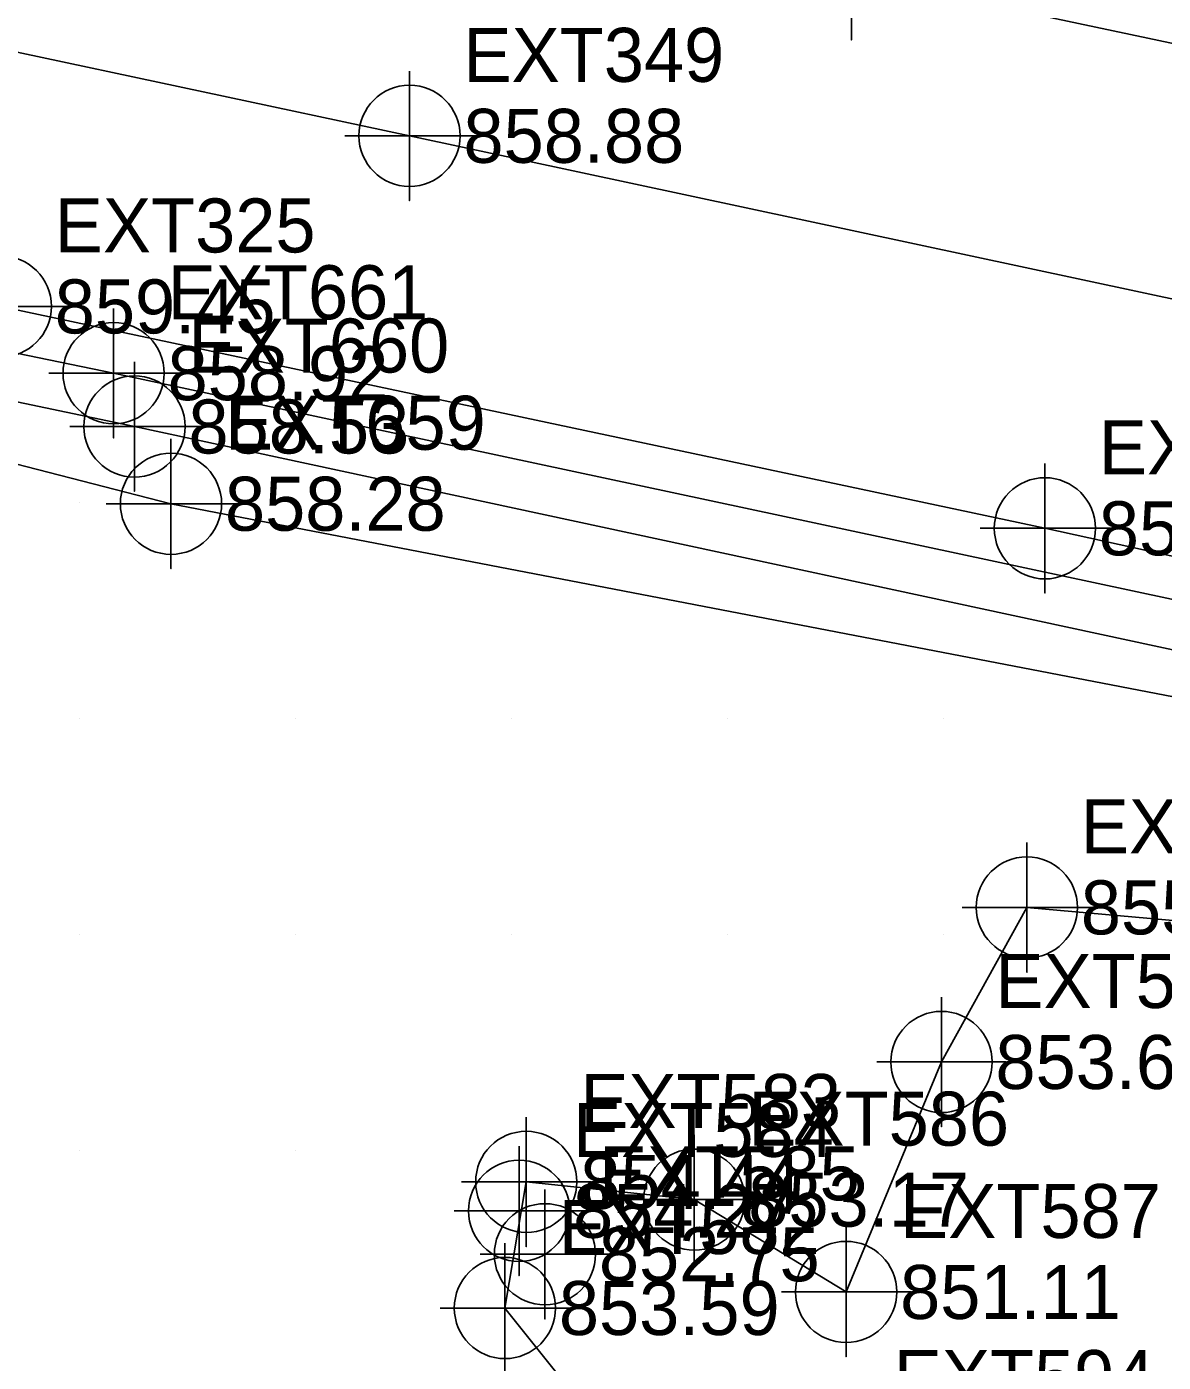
# Model space of a CAD drawing. Extents: x 1762120 to 1766775, y 709485 to 712965.
# Drawn here: x 1762697.5 to 1762750.2, y 712600.2 to 712662 of the extents above; entities that cross this region are included whole.
import ezdxf

# ---------------------------------------------------------------- set-up
doc = ezdxf.new("R2010")
doc.units = 0
for name, color, linetype in [('Exist DTM Breakline', 7, 'Continuous'), ('Exist DTM Breakline Cogo Elevation', 7, 'Continuous'), ('Exist DTM Breakline Cogo Number', 7, 'Continuous'), ('Exist DTM Breakline Cogo Point CELL', 7, 'Continuous'), ('Exist DTM Crownline', 7, 'Continuous'), ('Exist DTM Crownline Cogo Elevation', 7, 'Continuous'), ('Exist DTM Crownline Cogo Number', 7, 'Continuous'), ('Exist DTM Crownline Cogo Point CELL', 7, 'Continuous'), ('Exist DTM Drainline Cogo Elevation', 7, 'Continuous'), ('Exist DTM Drainline Cogo Number', 7, 'Continuous'), ('Exist DTM Drainline Cogo Point CELL', 7, 'Continuous'), ('Exist DTM QL2 LIDAR Elevation Point', 7, 'Continuous'), ('Exist Roads EOP', 7, 'Continuous'), ('Exist Roads EOP Cogo Elevation', 7, 'Continuous'), ('Exist Roads EOP Cogo Number', 7, 'Continuous'), ('Exist Roads EOP Cogo Point CELL', 7, 'Continuous'), ('Exist Utilities Telephone UG FO SUE LOS C', 7, 'Continuous'), ('Exist Utilities Telephone UG FO SUE LOS C Cogo Elevation', 7, 'Continuous'), ('Exist Utilities Telephone UG FO SUE LOS C Cogo Number', 7, 'Continuous'), ('Exist Utilities Telephone UG FO SUE LOS C Cogo Point CELL', 7, 'Continuous'), ('Exist Utilities Water UG Line SUE LOS C', 7, 'Continuous'), ('Exist Utilities Water UG Line SUE LOS C Cogo Elevation', 7, 'Continuous'), ('Exist Utilities Water UG Line SUE LOS C Cogo Number', 7, 'Continuous'), ('Exist Utilities Water UG Line SUE LOS C Cogo Point CELL', 7, 'Continuous')]:
    doc.layers.add(name, color=color, linetype=linetype)

msp = doc.modelspace()

# ---------------------------------------------------------------- linework, layer by layer
at = {"layer": 'Exist DTM Breakline'}
msp.add_lwpolyline([(1762719.497, 712557.512), (1762723.372, 712579.212), (1762728.166, 712592.081), (1762719.687, 712602.684), (1762720.676, 712608.523), (1762728.459, 712607.703), (1762735.491, 712603.427), (1762739.908, 712614.078), (1762743.864, 712621.238), (1762758.622, 712619.916), (1762767.954, 712615.272), (1762785.326, 712612.968), (1762818.774, 712608.043), (1762844.339, 712603.197), (1762875.474, 712595.472), (1762904.983, 712592.7), (1762941.56, 712585.948), (1762969.552, 712578.669)], dxfattribs=at)
at = {"layer": 'Exist DTM Breakline Cogo Point CELL'}
for points in [[(1762743.864, 712624.238), (1762743.864, 712618.238), (1762743.864, 712621.238), (1762746.864, 712621.238), (1762740.864, 712621.238)], [(1762739.908, 712617.078), (1762739.908, 712611.078), (1762739.908, 712614.078), (1762742.908, 712614.078), (1762736.908, 712614.078)], [(1762720.676, 712611.523), (1762720.676, 712605.523), (1762720.676, 712608.523), (1762723.676, 712608.523), (1762717.676, 712608.523)], [(1762728.459, 712610.703), (1762728.459, 712604.703), (1762728.459, 712607.703), (1762731.459, 712607.703), (1762725.459, 712607.703)], [(1762735.491, 712606.427), (1762735.491, 712600.427), (1762735.491, 712603.427), (1762738.491, 712603.427), (1762732.491, 712603.427)], [(1762719.687, 712605.684), (1762719.687, 712599.684), (1762719.687, 712602.684), (1762722.687, 712602.684), (1762716.687, 712602.684)]]:
    msp.add_lwpolyline(points, dxfattribs=at)
for centre in [(1762743.864, 712621.238), (1762739.908, 712614.078), (1762720.676, 712608.523), (1762728.459, 712607.703), (1762735.491, 712603.427), (1762719.687, 712602.684)]:
    msp.add_circle(centre, 2.344, dxfattribs=at)
at = {"layer": 'Exist DTM Crownline'}
msp.add_lwpolyline([(1762166.547, 712774.687), (1762217.293, 712763.929), (1762266.928, 712753.164), (1762315.989, 712742.645), (1762361.304, 712733.127), (1762409.518, 712722.711), (1762461.505, 712711.505), (1762512.117, 712700.307), (1762561.004, 712689.861), (1762611.478, 712678.845), (1762663.765, 712667.96), (1762715.266, 712656.972), (1762767.733, 712645.753), (1762820.16, 712634.416), (1762873.558, 712623.116), (1762907.318, 712615.867), (1762954.844, 712607.608), (1762970.656, 712604.722)], dxfattribs=at)
at = {"layer": 'Exist DTM Crownline Cogo Point CELL'}
msp.add_lwpolyline([(1762715.266, 712659.972), (1762715.266, 712653.972), (1762715.266, 712656.972), (1762718.266, 712656.972), (1762712.266, 712656.972)], dxfattribs=at)
msp.add_circle((1762715.266, 712656.972), 2.344, dxfattribs=at)
at = {"layer": 'Exist DTM Drainline Cogo Point CELL'}
for points in [[(1762720.343, 712610.184), (1762720.343, 712604.184), (1762720.343, 712607.184), (1762723.343, 712607.184), (1762717.343, 712607.184)], [(1762721.541, 712608.172), (1762721.541, 712602.172), (1762721.541, 712605.172), (1762724.541, 712605.172), (1762718.541, 712605.172)]]:
    msp.add_lwpolyline(points, dxfattribs=at)
for centre in [(1762720.343, 712607.184), (1762721.541, 712605.172)]:
    msp.add_circle(centre, 2.344, dxfattribs=at)
at = {"layer": 'Exist DTM QL2 LIDAR Elevation Point'}
for p, q in [((1762700, 712640), (1762700, 712640)), ((1762710, 712640), (1762710, 712640)), ((1762720, 712640), (1762720, 712640)), ((1762700, 712630), (1762700, 712630)), ((1762710, 712630), (1762710, 712630)), ((1762720, 712630), (1762720, 712630)), ((1762730, 712630), (1762730, 712630)), ((1762740, 712630), (1762740, 712630)), ((1762700, 712620), (1762700, 712620)), ((1762710, 712620), (1762710, 712620)), ((1762720, 712620), (1762720, 712620)), ((1762730, 712620), (1762730, 712620)), ((1762740, 712620), (1762740, 712620)), ((1762700, 712610), (1762700, 712610)), ((1762710, 712610), (1762710, 712610)), ((1762730, 712610), (1762730, 712610))]:
    msp.add_line(p, q, dxfattribs=at)
at = {"layer": 'Exist Roads EOP'}
for points in [[(1762972.643, 712616.327), (1762930.479, 712622.907), (1762881.99, 712633.196), (1762831.971, 712644.063), (1762782.816, 712654.409), (1762735.737, 712664.412), (1762686.68, 712675.525), (1762639.564, 712685.265), (1762589.399, 712696.151), (1762546.232, 712705.49), (1762496.404, 712716.081), (1762446.151, 712726.895), (1762396.234, 712737.694), (1762346.428, 712748.231), (1762295.972, 712759.182), (1762245.105, 712770.099), (1762193.683, 712780.972), (1762169.004, 712786.417)], [(1762974.578, 712585.314), (1762927.979, 712597.842), (1762890.673, 712606.296), (1762842.51, 712617.09), (1762793.23, 712628.151), (1762744.7, 712638.794), (1762696.334, 712649.071), (1762645.671, 712659.578), (1762597.313, 712669.972), (1762548.878, 712680.543), (1762499.868, 712691.039), (1762451.782, 712701.31), (1762402.083, 712712.161), (1762353.635, 712722.593), (1762304.798, 712733.112), (1762255.134, 712743.654), (1762207.339, 712753.911), (1762164.278, 712763.059), (1762150.692, 712765.782)]]:
    msp.add_lwpolyline(points, dxfattribs=at)
at = {"layer": 'Exist Roads EOP Cogo Point CELL'}
for points in [[(1762735.737, 712667.412), (1762735.737, 712661.412), (1762735.737, 712664.412), (1762738.737, 712664.412), (1762732.737, 712664.412)], [(1762696.334, 712652.071), (1762696.334, 712646.071), (1762696.334, 712649.071), (1762699.334, 712649.071), (1762693.334, 712649.071)], [(1762744.7, 712641.794), (1762744.7, 712635.794), (1762744.7, 712638.794), (1762747.7, 712638.794), (1762741.7, 712638.794)]]:
    msp.add_lwpolyline(points, dxfattribs=at)
for centre in [(1762696.334, 712649.071), (1762744.7, 712638.794)]:
    msp.add_circle(centre, 2.344, dxfattribs=at)
at = {"layer": 'Exist Utilities Telephone UG FO SUE LOS C'}
for points in [[(1762975.06, 712582.936), (1762942.128, 712590.141), (1762892.884, 712602.573), (1762845.987, 712612.29), (1762766.135, 712629.835), (1762702.526, 712643.51), (1762677.774, 712648.696)], [(1762974.378, 712580.101), (1762941.961, 712587.59), (1762882.884, 712601.621), (1762847.537, 712609.713), (1762765.896, 712628.049), (1762704.218, 712639.933), (1762682.076, 712645.625)]]:
    msp.add_lwpolyline(points, dxfattribs=at)
at = {"layer": 'Exist Utilities Telephone UG FO SUE LOS C Cogo Point CELL'}
for points in [[(1762702.526, 712646.51), (1762702.526, 712640.51), (1762702.526, 712643.51), (1762705.526, 712643.51), (1762699.526, 712643.51)], [(1762704.218, 712642.933), (1762704.218, 712636.933), (1762704.218, 712639.933), (1762707.218, 712639.933), (1762701.218, 712639.933)]]:
    msp.add_lwpolyline(points, dxfattribs=at)
for centre in [(1762702.526, 712643.51), (1762704.218, 712639.933)]:
    msp.add_circle(centre, 2.344, dxfattribs=at)
at = {"layer": 'Exist Utilities Water UG Line SUE LOS C'}
msp.add_lwpolyline([(1762975.806, 712587.967), (1762937.62, 712595.557), (1762895.763, 712604.028), (1762842.398, 712615.448), (1762766.685, 712632.078), (1762701.56, 712645.979), (1762676.599, 712651.124)], dxfattribs=at)
at = {"layer": 'Exist Utilities Water UG Line SUE LOS C Cogo Point CELL'}
msp.add_lwpolyline([(1762701.56, 712648.979), (1762701.56, 712642.979), (1762701.56, 712645.979), (1762704.56, 712645.979), (1762698.56, 712645.979)], dxfattribs=at)
msp.add_circle((1762701.56, 712645.979), 2.344, dxfattribs=at)

# ---------------------------------------------------------------- texts
at = {"layer": 'Exist DTM Breakline Cogo Elevation'}
for s, p in [('855.14', (1762746.364, 712619.988)), ('853.67', (1762742.408, 712612.828)), ('854.44', (1762723.176, 712607.273)), ('853.17', (1762730.959, 712606.453)), ('851.11', (1762737.991, 712602.177)), ('853.59', (1762722.187, 712601.434))]:
    msp.add_text(s, height=2.5, dxfattribs=at).set_placement(p)
at = {"layer": 'Exist DTM Breakline Cogo Number'}
for s, p in [('EXT589', (1762746.364, 712623.738)), ('EXT588', (1762742.408, 712616.578)), ('EXT583', (1762723.176, 712611.023)), ('EXT586', (1762730.959, 712610.203)), ('EXT587', (1762737.991, 712605.927)), ('EXT582', (1762722.187, 712605.184))]:
    msp.add_text(s, height=2.5, dxfattribs=at).set_placement(p)
at = {"layer": 'Exist DTM Crownline Cogo Elevation'}
msp.add_text('858.88', height=2.5, dxfattribs=at).set_placement((1762717.766, 712655.722))
at = {"layer": 'Exist DTM Crownline Cogo Number'}
msp.add_text('EXT349', height=2.5, dxfattribs=at).set_placement((1762717.766, 712659.472))
at = {"layer": 'Exist DTM Drainline Cogo Elevation'}
for s, p in [('854.27', (1762722.843, 712605.934)), ('852.75', (1762724.041, 712603.922))]:
    msp.add_text(s, height=2.5, dxfattribs=at).set_placement(p)
at = {"layer": 'Exist DTM Drainline Cogo Number'}
for s, p in [('EXT584', (1762722.843, 712609.684)), ('EXT585', (1762724.041, 712607.672)), ('EXT594', (1762737.699, 712598.236))]:
    msp.add_text(s, height=2.5, dxfattribs=at).set_placement(p)
at = {"layer": 'Exist Roads EOP Cogo Elevation'}
for s, p in [('859.45', (1762698.834, 712647.821)), ('857.21', (1762747.2, 712637.544))]:
    msp.add_text(s, height=2.5, dxfattribs=at).set_placement(p)
at = {"layer": 'Exist Roads EOP Cogo Number'}
for s, p in [('EXT325', (1762698.834, 712651.571)), ('EXT324', (1762747.2, 712641.294))]:
    msp.add_text(s, height=2.5, dxfattribs=at).set_placement(p)
at = {"layer": 'Exist Utilities Telephone UG FO SUE LOS C Cogo Elevation'}
for s, p in [('858.53', (1762705.026, 712642.26)), ('858.28', (1762706.718, 712638.683))]:
    msp.add_text(s, height=2.5, dxfattribs=at).set_placement(p)
at = {"layer": 'Exist Utilities Telephone UG FO SUE LOS C Cogo Number'}
for s, p in [('EXT660', (1762705.026, 712646.01)), ('EXT659', (1762706.718, 712642.433))]:
    msp.add_text(s, height=2.5, dxfattribs=at).set_placement(p)
at = {"layer": 'Exist Utilities Water UG Line SUE LOS C Cogo Elevation'}
msp.add_text('858.92', height=2.5, dxfattribs=at).set_placement((1762704.06, 712644.729))
at = {"layer": 'Exist Utilities Water UG Line SUE LOS C Cogo Number'}
msp.add_text('EXT661', height=2.5, dxfattribs=at).set_placement((1762704.06, 712648.479))

doc.saveas('drawing.dxf')
